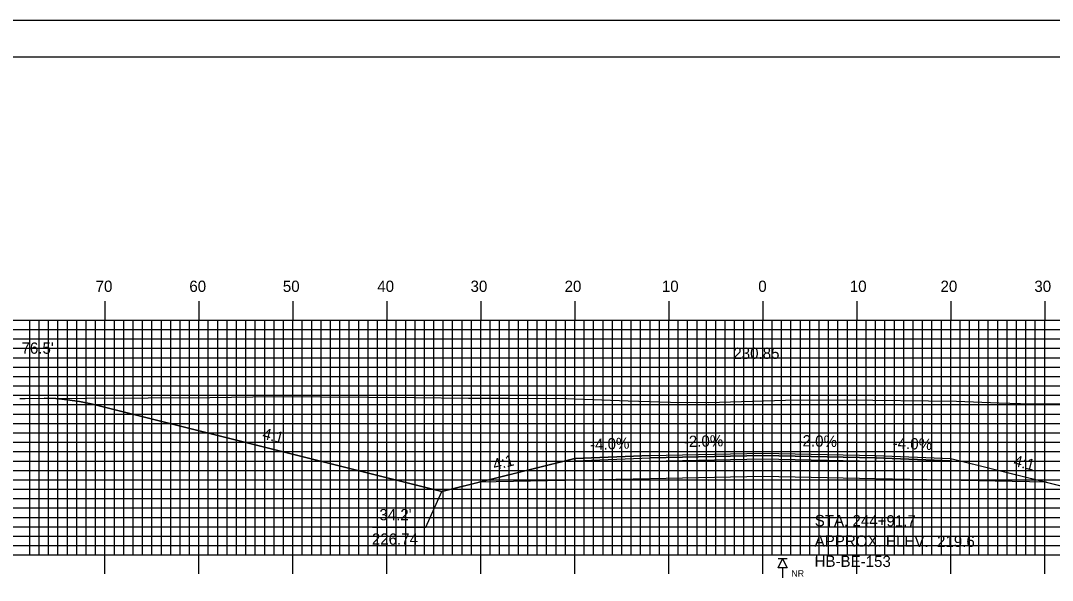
# Model space of a CAD drawing. Extents: x 1802716 to 1803060, y 442591 to 442811.
# Drawn here: x 1802803.1 to 1802912.9, y 442751 to 442810.5 of the extents above; entities that cross this region are included whole.
import ezdxf

# ---------------------------------------------------------------- set-up
doc = ezdxf.new("R2010")
doc.units = 0
for name, color, linetype in [('ANNOTATION', 7, 'Continuous'), ('BORDER', 7, 'Continuous'), ('BORING - NO REFUSAL', 7, 'Continuous'), ('D_Roadway_Centerline', 7, 'Continuous'), ('D_Roadway_Centerline_Text', 7, 'Continuous'), ('D_Roadway_Edge_Shoulder', 7, 'Continuous'), ('D_Roadway_Edge_TW', 7, 'Continuous'), ('D_Roadway_Pavement', 7, 'Continuous'), ('D_Roadway_SlopeLines', 7, 'Continuous'), ('D_Roadway_SubGrade', 7, 'Continuous'), ('D_Text_Standard', 7, 'Continuous'), ('H_V ANNOTATION', 7, 'Continuous'), ('MAJOR', 7, 'Continuous'), ('MINOR', 7, 'Continuous'), ('PLOT BOUNDARY', 7, 'Continuous'), ('S_Roadway_Centerline', 7, 'Continuous')]:
    doc.layers.add(name, color=color, linetype=linetype)

msp = doc.modelspace()

# ---------------------------------------------------------------- linework, layer by layer
at = {"layer": 'ANNOTATION'}
msp.add_lwpolyline([(1802840.57, 442756.63), (1802846.26, 442756.63), (1802847.94, 442760.41)], dxfattribs=at)
at = {"layer": 'BORDER'}
msp.add_lwpolyline([(1802732.51, 442596.67), (1803052.51, 442596.67), (1803052.51, 442806.67), (1802732.51, 442806.67)], close=True, dxfattribs=at)
at = {"layer": 'BORING - NO REFUSAL'}
for p, q in [((1802884.69, 442753.27), (1802883.73, 442753.27)), ((1802884.21, 442752.31), (1802884.21, 442751.25))]:
    msp.add_line(p, q, dxfattribs=at)
msp.add_lwpolyline([(1802884.21, 442753.27), (1802884.69, 442752.31), (1802883.73, 442752.31)], close=True, dxfattribs=at)
at = {"layer": 'D_Roadway_Centerline'}
msp.add_lwpolyline([(1802805.64, 442770.35), (1802806.89, 442770.32), (1802808.14, 442770.2), (1802809.39, 442770.01), (1802810.64, 442769.74), (1802847.94, 442760.41), (1802851.94, 442761.41), (1802862.11, 442763.95), (1802870.11, 442764.27), (1802882.11, 442764.51), (1802894.11, 442764.27), (1802902.11, 442763.95), (1802912.29, 442761.41), (1802916.29, 442760.41), (1802950.28, 442768.91), (1802951.53, 442769.18), (1802952.78, 442769.37), (1802954.03, 442769.48), (1802955.28, 442769.51)], dxfattribs=at)
at = {"layer": 'D_Roadway_Edge_Shoulder'}
for points in [[(1802870.11, 442764.27), (1802862.11, 442763.95), (1802862.11, 442763.7), (1802870.11, 442764.02)], [(1802894.11, 442764.27), (1802902.11, 442763.95), (1802902.11, 442763.7), (1802894.11, 442764.02)]]:
    msp.add_lwpolyline(points, close=True, dxfattribs=at)
at = {"layer": 'D_Roadway_Edge_TW'}
msp.add_lwpolyline([(1802870.11, 442764.02), (1802870.11, 442764.27), (1802882.11, 442764.51), (1802894.11, 442764.27), (1802894.11, 442764.02), (1802882.11, 442764.26)], close=True, dxfattribs=at)
at = {"layer": 'D_Roadway_Pavement'}
msp.add_lwpolyline([(1802870.11, 442763.61), (1802870.11, 442764.02), (1802882.11, 442764.26), (1802894.11, 442764.02), (1802894.11, 442763.61), (1802882.11, 442763.85)], close=True, dxfattribs=at)
at = {"layer": 'D_Roadway_SlopeLines'}
for points in [[(1802847.94, 442760.41), (1802810.64, 442769.74), (1802809.39, 442770.01), (1802808.14, 442770.2), (1802806.89, 442770.32), (1802805.64, 442770.35)], [(1802862.11, 442763.95), (1802847.94, 442760.41)], [(1802902.11, 442763.95), (1802916.29, 442760.41)]]:
    msp.add_lwpolyline(points, dxfattribs=at)
at = {"layer": 'D_Roadway_SubGrade'}
msp.add_lwpolyline([(1802870.11, 442761.77), (1802851.94, 442761.41), (1802862.11, 442763.95), (1802862.11, 442763.7), (1802870.11, 442764.02), (1802882.11, 442764.26), (1802894.11, 442764.02), (1802902.11, 442763.7), (1802902.11, 442763.95), (1802912.29, 442761.41), (1802894.11, 442761.77), (1802882.11, 442762.01)], close=True, dxfattribs=at)
at = {"layer": 'MAJOR'}
for p, q in [((1802812.11, 442780.67), (1802812.11, 442778.67)), ((1802822.11, 442780.67), (1802822.11, 442778.67)), ((1802832.11, 442780.67), (1802832.11, 442778.67)), ((1802842.11, 442780.67), (1802842.11, 442778.67)), ((1802852.11, 442780.67), (1802852.11, 442778.67)), ((1802862.11, 442780.67), (1802862.11, 442778.67)), ((1802872.11, 442780.67), (1802872.11, 442778.67)), ((1802882.11, 442780.67), (1802882.11, 442778.67)), ((1802892.11, 442780.67), (1802892.11, 442778.67)), ((1802902.11, 442780.67), (1802902.11, 442778.67)), ((1802912.11, 442780.67), (1802912.11, 442778.67)), ((1802742.11, 442778.67), (1803022.11, 442778.67)), ((1802742.11, 442778.67), (1803022.11, 442778.67)), ((1802812.11, 442753.67), (1802812.11, 442778.67)), ((1802822.11, 442753.67), (1802822.11, 442778.67)), ((1802832.11, 442753.67), (1802832.11, 442778.67)), ((1802842.11, 442753.67), (1802842.11, 442778.67)), ((1802852.11, 442753.67), (1802852.11, 442778.67)), ((1802862.11, 442753.67), (1802862.11, 442778.67)), ((1802872.11, 442753.67), (1802872.11, 442778.67)), ((1802882.11, 442753.67), (1802882.11, 442778.67)), ((1802892.11, 442753.67), (1802892.11, 442778.67)), ((1802902.11, 442753.67), (1802902.11, 442778.67)), ((1802912.11, 442753.67), (1802912.11, 442778.67)), ((1802742.11, 442773.67), (1803022.11, 442773.67)), ((1802742.11, 442768.67), (1803022.11, 442768.67)), ((1802742.11, 442763.67), (1803022.11, 442763.67)), ((1802742.11, 442758.67), (1803022.11, 442758.67)), ((1802742.11, 442753.67), (1803022.11, 442753.67)), ((1802742.11, 442753.67), (1803022.11, 442753.67)), ((1802812.11, 442751.66), (1802812.11, 442753.67)), ((1802822.11, 442751.66), (1802822.11, 442753.67)), ((1802832.11, 442751.66), (1802832.11, 442753.67)), ((1802842.11, 442751.66), (1802842.11, 442753.67)), ((1802852.11, 442751.66), (1802852.11, 442753.67)), ((1802862.11, 442751.66), (1802862.11, 442753.67)), ((1802872.11, 442751.66), (1802872.11, 442753.67)), ((1802882.11, 442751.66), (1802882.11, 442753.67)), ((1802892.11, 442751.66), (1802892.11, 442753.67)), ((1802902.11, 442751.66), (1802902.11, 442753.67)), ((1802912.11, 442751.66), (1802912.11, 442753.67))]:
    msp.add_line(p, q, dxfattribs=at)
at = {"layer": 'MINOR'}
for p, q in [((1802804.11, 442753.67), (1802804.11, 442778.67)), ((1802805.11, 442753.67), (1802805.11, 442778.67)), ((1802806.11, 442753.67), (1802806.11, 442778.67)), ((1802807.11, 442753.67), (1802807.11, 442778.67)), ((1802808.11, 442753.67), (1802808.11, 442778.67)), ((1802809.11, 442753.67), (1802809.11, 442778.67)), ((1802810.11, 442753.67), (1802810.11, 442778.67)), ((1802811.11, 442753.67), (1802811.11, 442778.67)), ((1802813.11, 442753.67), (1802813.11, 442778.67)), ((1802814.11, 442753.67), (1802814.11, 442778.67)), ((1802815.11, 442753.67), (1802815.11, 442778.67)), ((1802816.11, 442753.67), (1802816.11, 442778.67)), ((1802817.11, 442753.67), (1802817.11, 442778.67)), ((1802818.11, 442753.67), (1802818.11, 442778.67)), ((1802819.11, 442753.67), (1802819.11, 442778.67)), ((1802820.11, 442753.67), (1802820.11, 442778.67)), ((1802821.11, 442753.67), (1802821.11, 442778.67)), ((1802823.11, 442753.67), (1802823.11, 442778.67)), ((1802824.11, 442753.67), (1802824.11, 442778.67)), ((1802825.11, 442753.67), (1802825.11, 442778.67)), ((1802826.11, 442753.67), (1802826.11, 442778.67)), ((1802827.11, 442753.67), (1802827.11, 442778.67)), ((1802828.11, 442753.67), (1802828.11, 442778.67)), ((1802829.11, 442753.67), (1802829.11, 442778.67)), ((1802830.11, 442753.67), (1802830.11, 442778.67)), ((1802831.11, 442753.67), (1802831.11, 442778.67)), ((1802833.11, 442753.67), (1802833.11, 442778.67)), ((1802834.11, 442753.67), (1802834.11, 442778.67)), ((1802835.11, 442753.67), (1802835.11, 442778.67)), ((1802836.11, 442753.67), (1802836.11, 442778.67)), ((1802837.11, 442753.67), (1802837.11, 442778.67)), ((1802838.11, 442753.67), (1802838.11, 442778.67)), ((1802839.11, 442753.67), (1802839.11, 442778.67)), ((1802840.11, 442753.67), (1802840.11, 442778.67)), ((1802841.11, 442753.67), (1802841.11, 442778.67)), ((1802843.11, 442753.67), (1802843.11, 442778.67)), ((1802844.11, 442753.67), (1802844.11, 442778.67)), ((1802845.11, 442753.67), (1802845.11, 442778.67)), ((1802846.11, 442753.67), (1802846.11, 442778.67)), ((1802847.11, 442753.67), (1802847.11, 442778.67)), ((1802848.11, 442753.67), (1802848.11, 442778.67)), ((1802849.11, 442753.67), (1802849.11, 442778.67)), ((1802850.11, 442753.67), (1802850.11, 442778.67)), ((1802851.11, 442753.67), (1802851.11, 442778.67)), ((1802853.11, 442753.67), (1802853.11, 442778.67)), ((1802854.11, 442753.67), (1802854.11, 442778.67)), ((1802855.11, 442753.67), (1802855.11, 442778.67)), ((1802856.11, 442753.67), (1802856.11, 442778.67)), ((1802857.11, 442753.67), (1802857.11, 442778.67)), ((1802858.11, 442753.67), (1802858.11, 442778.67)), ((1802859.11, 442753.67), (1802859.11, 442778.67)), ((1802860.11, 442753.67), (1802860.11, 442778.67)), ((1802861.11, 442753.67), (1802861.11, 442778.67)), ((1802863.11, 442753.67), (1802863.11, 442778.67)), ((1802864.11, 442753.67), (1802864.11, 442778.67)), ((1802865.11, 442753.67), (1802865.11, 442778.67)), ((1802866.11, 442753.67), (1802866.11, 442778.67)), ((1802867.11, 442753.67), (1802867.11, 442778.67)), ((1802868.11, 442753.67), (1802868.11, 442778.67)), ((1802869.11, 442753.67), (1802869.11, 442778.67)), ((1802870.11, 442753.67), (1802870.11, 442778.67)), ((1802871.11, 442753.67), (1802871.11, 442778.67)), ((1802873.11, 442753.67), (1802873.11, 442778.67)), ((1802874.11, 442753.67), (1802874.11, 442778.67)), ((1802875.11, 442753.67), (1802875.11, 442778.67)), ((1802876.11, 442753.67), (1802876.11, 442778.67)), ((1802877.11, 442753.67), (1802877.11, 442778.67)), ((1802878.11, 442753.67), (1802878.11, 442778.67)), ((1802879.11, 442753.67), (1802879.11, 442778.67)), ((1802880.11, 442753.67), (1802880.11, 442778.67)), ((1802881.11, 442753.67), (1802881.11, 442778.67)), ((1802883.11, 442753.67), (1802883.11, 442778.67)), ((1802884.11, 442753.67), (1802884.11, 442778.67)), ((1802885.11, 442753.67), (1802885.11, 442778.67)), ((1802886.11, 442753.67), (1802886.11, 442778.67)), ((1802887.11, 442753.67), (1802887.11, 442778.67)), ((1802888.11, 442753.67), (1802888.11, 442778.67)), ((1802889.11, 442753.67), (1802889.11, 442778.67)), ((1802890.11, 442753.67), (1802890.11, 442778.67)), ((1802891.11, 442753.67), (1802891.11, 442778.67)), ((1802893.11, 442753.67), (1802893.11, 442778.67)), ((1802894.11, 442753.67), (1802894.11, 442778.67)), ((1802895.11, 442753.67), (1802895.11, 442778.67)), ((1802896.11, 442753.67), (1802896.11, 442778.67)), ((1802897.11, 442753.67), (1802897.11, 442778.67)), ((1802898.11, 442753.67), (1802898.11, 442778.67)), ((1802899.11, 442753.67), (1802899.11, 442778.67)), ((1802900.11, 442753.67), (1802900.11, 442778.67)), ((1802901.11, 442753.67), (1802901.11, 442778.67)), ((1802903.11, 442753.67), (1802903.11, 442778.67)), ((1802904.11, 442753.67), (1802904.11, 442778.67)), ((1802905.11, 442753.67), (1802905.11, 442778.67)), ((1802906.11, 442753.67), (1802906.11, 442778.67)), ((1802907.11, 442753.67), (1802907.11, 442778.67)), ((1802908.11, 442753.67), (1802908.11, 442778.67)), ((1802909.11, 442753.67), (1802909.11, 442778.67)), ((1802910.11, 442753.67), (1802910.11, 442778.67)), ((1802911.11, 442753.67), (1802911.11, 442778.67)), ((1802742.11, 442777.67), (1803022.11, 442777.67)), ((1802742.11, 442776.67), (1803022.11, 442776.67)), ((1802742.11, 442775.67), (1803022.11, 442775.67)), ((1802742.11, 442774.67), (1803022.11, 442774.67)), ((1802742.11, 442772.67), (1803022.11, 442772.67)), ((1802742.11, 442771.67), (1803022.11, 442771.67)), ((1802742.11, 442770.67), (1803022.11, 442770.67)), ((1802742.11, 442769.67), (1803022.11, 442769.67)), ((1802742.11, 442767.67), (1803022.11, 442767.67)), ((1802742.11, 442766.67), (1803022.11, 442766.67)), ((1802742.11, 442765.67), (1803022.11, 442765.67)), ((1802742.11, 442764.67), (1803022.11, 442764.67)), ((1802742.11, 442762.67), (1803022.11, 442762.67)), ((1802742.11, 442761.67), (1803022.11, 442761.67)), ((1802742.11, 442760.67), (1803022.11, 442760.67)), ((1802742.11, 442759.67), (1803022.11, 442759.67)), ((1802742.11, 442757.67), (1803022.11, 442757.67)), ((1802742.11, 442756.67), (1803022.11, 442756.67)), ((1802742.11, 442755.67), (1803022.11, 442755.67)), ((1802742.11, 442754.67), (1803022.11, 442754.67))]:
    msp.add_line(p, q, dxfattribs=at)
at = {"layer": 'PLOT BOUNDARY'}
msp.add_lwpolyline([(1802716.33, 442590.55), (1803056.33, 442590.55), (1803056.33, 442810.55), (1802716.33, 442810.55)], close=True, dxfattribs=at)
at = {"layer": 'S_Roadway_Centerline'}
msp.add_lwpolyline([(1802803.04, 442770.34), (1802803.62, 442770.34), (1802823.27, 442770.42), (1802830.16, 442770.55), (1802845.01, 442770.43), (1802850.79, 442770.37), (1802855.06, 442770.37), (1802861.22, 442770.33), (1802867.78, 442770.06), (1802872.3, 442769.93), (1802876.35, 442769.91), (1802884.51, 442770.13), (1802890.85, 442770.2), (1802902.71, 442770.04), (1802907.23, 442769.88), (1802910.69, 442769.77), (1802918.81, 442769.76)], dxfattribs=at)

# ---------------------------------------------------------------- texts
at = {"layer": 'ANNOTATION'}
for s, rotation, p in [('4:1', 345.9638, (1802828.79, 442766.06)), ('-4.0%', 2.2906, (1802863.75, 442764.82)), ('-2.0%', 1.1458, (1802873.72, 442765.15)), ('-2.0%', 358.8542, (1802885.8, 442765.24)), ('-4.0%', 357.7094, (1802895.91, 442765)), ('4:1', 14.0362, (1802853.56, 442762.68)), ('4:1', 345.9638, (1802908.71, 442763.17))]:
    msp.add_text(s, height=1.2, rotation=rotation, dxfattribs=at).set_placement(p)
for s, p in [("34.2'", (1802841.31, 442757.36)), ('226.74', (1802840.51, 442754.76))]:
    msp.add_text(s, height=1.2, dxfattribs=at).set_placement(p)
at = {"layer": 'BORING - NO REFUSAL'}
for s, p in [('STA. 244+91.7', (1802887.64, 442756.73)), ('APPROX. ELEV.  219.6', (1802887.63, 442754.57)), ('HB-BE-153', (1802887.62, 442752.41))]:
    msp.add_text(s, height=1.2, rotation=359.8142, dxfattribs=at).set_placement(p)
msp.add_text('NR', height=0.7, dxfattribs=at).set_placement((1802885.15, 442751.35))
at = {"layer": 'D_Roadway_Centerline'}
for s in ['C', 'L']:
    msp.add_text(s, height=0.0146, dxfattribs=at).set_placement((1802882.11, 442764.51))
at = {"layer": 'D_Roadway_Centerline_Text'}
msp.add_text('230.85', height=1.2, dxfattribs=at).set_placement((1802878.98, 442774.54))
at = {"layer": 'D_Text_Standard'}
msp.add_text("76.5'", height=1.2, dxfattribs=at).set_placement((1802803.23, 442775.09))
at = {"layer": 'H_V ANNOTATION'}
for s, p in [('70', (1802811.12, 442781.67)), ('60', (1802821.09, 442781.67)), ('50', (1802831.04, 442781.67)), ('40', (1802841.09, 442781.67)), ('30', (1802851.01, 442781.67)), ('20', (1802861.02, 442781.67)), ('10', (1802871.37, 442781.67)), ('0', (1802881.63, 442781.67)), ('10', (1802891.37, 442781.67)), ('20', (1802901.02, 442781.67)), ('30', (1802911.01, 442781.67))]:
    msp.add_text(s, height=1.2, dxfattribs=at).set_placement(p)

doc.saveas('drawing.dxf')
